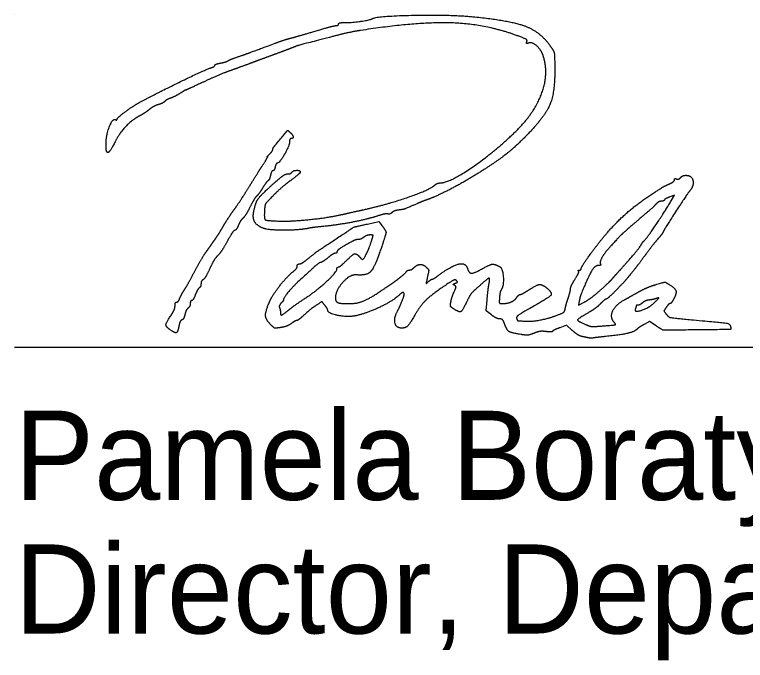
# Model space of a CAD drawing. Extents: x 0 to 34, y -1.6 to 22.
# Drawn here: x 24.528 to 25.676, y 8.599 to 9.614 of the extents above; entities that cross this region are included whole.
import ezdxf

# ---------------------------------------------------------------- set-up
doc = ezdxf.new("R2010")
doc.units = 0
doc.layers.add('SH_Data', color=7, linetype='Continuous')
doc.layers.add('SH_Text', color=7, linetype='Continuous')

msp = doc.modelspace()

# ---------------------------------------------------------------- linework, layer by layer
at = {"layer": 'SH_Data'}
for p, q in [((24.5279, 9.6139), (24.5279, 9.6139)), ((24.5279, 9.0916), (28.0279, 9.0916))]:
    msp.add_line(p, q, dxfattribs=at)
at = {"layer": 'SH_Text'}
for points in [[(25.5597, 9.3211), (25.5651, 9.33), (25.5577, 9.3274)], [(25.0824, 9.2849), (25.1004, 9.289), (25.1051, 9.2828)], [(25.2773, 9.1421), (25.269, 9.1484), (25.2704, 9.1655)], [(25.4153, 9.1641), (25.4143, 9.1576), (25.4229, 9.1621)], [(25.5361, 9.1248), (25.5255, 9.1316), (25.5171, 9.1271)], [(25.4043, 9.1178), (25.3951, 9.1261), (25.3845, 9.122)]]:
    msp.add_lwpolyline(points, dxfattribs=at)
for points in [[(25.0898, 9.6075), (25.0966, 9.6117), (25.2136, 9.614), (25.248, 9.6106)], [(25.0368, 9.5991), (25.0368, 9.6004), (25.0408, 9.6014), (25.0458, 9.6013)], [(25.0458, 9.6013), (25.0554, 9.601), (25.0864, 9.6054), (25.0898, 9.6075)], [(25.3205, 9.5798), (25.2699, 9.5988), (25.1619, 9.6028), (25.0716, 9.589)], [(25.248, 9.6106), (25.3072, 9.6047), (25.3548, 9.5865), (25.3706, 9.5634)], [(25, 9.5879), (25.0161, 9.5927), (25.031, 9.5966), (25.033, 9.5966)], [(25.033, 9.5966), (25.0351, 9.5966), (25.0368, 9.5977), (25.0368, 9.5991)], [(24.9612, 9.5768), (24.9665, 9.5781), (24.9839, 9.5831), (25, 9.5879)], [(25.0272, 9.5793), (24.9762, 9.5661), (24.9719, 9.5649), (24.9612, 9.5606)], [(25.0716, 9.589), (25.0623, 9.5876), (25.0424, 9.5833), (25.0272, 9.5793)], [(25.3328, 9.5712), (25.3338, 9.5737), (25.3303, 9.5761), (25.3205, 9.5798)], [(24.8808, 9.5483), (24.8955, 9.5534), (24.9019, 9.5558), (24.9372, 9.5689)], [(24.9372, 9.5689), (24.9451, 9.5719), (24.9559, 9.5754), (24.9612, 9.5768)], [(25.3352, 9.5691), (25.3326, 9.5681), (25.3319, 9.5688), (25.3328, 9.5712)], [(25.3586, 9.5492), (25.3553, 9.559), (25.3409, 9.5713), (25.3352, 9.5691)], [(24.9612, 9.5606), (24.9585, 9.5595), (24.9483, 9.5557), (24.9384, 9.5521)], [(25.3706, 9.5634), (25.3755, 9.5562), (25.3764, 9.5518), (25.3768, 9.534)], [(24.8628, 9.5412), (24.8641, 9.5421), (24.8722, 9.5454), (24.8808, 9.5483)], [(24.9384, 9.5521), (24.9285, 9.5485), (24.9134, 9.5429), (24.9048, 9.5397)], [(25.3131, 9.428), (25.344, 9.4575), (25.3679, 9.521), (25.3586, 9.5492)], [(24.837, 9.5305), (24.84, 9.5314), (24.8424, 9.533), (24.8424, 9.534)], [(24.8424, 9.534), (24.8424, 9.5351), (24.8464, 9.5368), (24.8514, 9.5377)], [(24.8514, 9.5377), (24.8563, 9.5386), (24.8615, 9.5402), (24.8628, 9.5412)], [(24.9048, 9.5397), (24.8962, 9.5364), (24.88, 9.5305), (24.8688, 9.5265)], [(25.3768, 9.534), (25.3775, 9.4932), (25.3614, 9.4535), (25.332, 9.4236)], [(24.7248, 9.4762), (24.755, 9.4924), (24.8286, 9.528), (24.837, 9.5305)], [(24.8688, 9.5265), (24.8576, 9.5226), (24.8372, 9.514), (24.8236, 9.5075)], [(24.8236, 9.5075), (24.8099, 9.5011), (24.7983, 9.4958), (24.7977, 9.4958)], [(24.7877, 9.4901), (24.7828, 9.487), (24.7761, 9.4836), (24.7729, 9.4826)], [(24.7977, 9.4958), (24.7971, 9.4958), (24.7927, 9.4932), (24.7877, 9.4901)], [(24.6888, 9.4495), (24.6888, 9.4517), (24.7142, 9.4705), (24.7248, 9.4762)], [(24.7637, 9.4774), (24.7619, 9.4756), (24.7576, 9.4735), (24.754, 9.4726)], [(24.7729, 9.4826), (24.7697, 9.4816), (24.7655, 9.4792), (24.7637, 9.4774)], [(24.7392, 9.4645), (24.7346, 9.4609), (24.7274, 9.4563), (24.7233, 9.4542)], [(24.754, 9.4726), (24.7505, 9.4717), (24.7438, 9.4681), (24.7392, 9.4645)], [(24.7233, 9.4542), (24.7129, 9.4489), (24.693, 9.428), (24.6868, 9.4159)], [(24.6716, 9.4117), (24.6717, 9.4249), (24.6823, 9.4515), (24.6865, 9.4489)], [(24.6865, 9.4489), (24.6877, 9.4481), (24.6888, 9.4484), (24.6888, 9.4495)], [(24.939, 9.4106), (24.9575, 9.4327), (24.9568, 9.4322), (24.9609, 9.4288)], [(24.9624, 9.419), (24.9611, 9.419), (24.96, 9.4167), (24.96, 9.4139)], [(24.9609, 9.4288), (24.9652, 9.4252), (24.9661, 9.419), (24.9624, 9.419)], [(25.1964, 9.3494), (25.2105, 9.3494), (25.2786, 9.3953), (25.3131, 9.428)], [(25.332, 9.4236), (25.3134, 9.4047), (25.281, 9.3798), (25.2505, 9.361)], [(24.673, 9.398), (24.6722, 9.3988), (24.6716, 9.4049), (24.6716, 9.4117)], [(24.6868, 9.4159), (24.6801, 9.403), (24.6748, 9.3961), (24.673, 9.398)], [(24.9336, 9.402), (24.9336, 9.4032), (24.936, 9.4071), (24.939, 9.4106)], [(24.96, 9.4139), (24.96, 9.4083), (24.9441, 9.3806), (24.9409, 9.3806)], [(24.925, 9.3902), (24.9245, 9.3902), (24.9261, 9.3923), (24.9288, 9.395)], [(24.9288, 9.395), (24.9314, 9.3976), (24.9336, 9.4007), (24.9336, 9.402)], [(24.916, 9.3745), (24.9216, 9.3831), (24.9256, 9.3902), (24.925, 9.3902)], [(24.894, 9.3395), (24.9006, 9.3501), (24.9105, 9.3659), (24.916, 9.3745)], [(24.9374, 9.3746), (24.9366, 9.3713), (24.9349, 9.3686), (24.9337, 9.3686)], [(24.9409, 9.3806), (24.9398, 9.3806), (24.9382, 9.3779), (24.9374, 9.3746)], [(24.9252, 9.3396), (24.9409, 9.3542), (24.9536, 9.3638), (24.9576, 9.3638)], [(24.93, 9.3614), (24.9291, 9.3574), (24.9274, 9.3536), (24.9261, 9.3528)], [(24.9337, 9.3686), (24.9325, 9.3686), (24.9309, 9.3653), (24.93, 9.3614)], [(24.9576, 9.3638), (24.9601, 9.3638), (24.9628, 9.3648), (24.9636, 9.3662)], [(24.9768, 9.3665), (24.9768, 9.3654), (24.97, 9.3595), (24.9618, 9.3534)], [(24.9636, 9.3662), (24.9654, 9.3691), (24.9768, 9.3694), (24.9768, 9.3665)], [(25.2505, 9.361), (25.2313, 9.3491), (25.1901, 9.3281), (25.176, 9.323)], [(25.5745, 9.3579), (25.5761, 9.3598), (25.5798, 9.3614), (25.5827, 9.3614)], [(25.5827, 9.3614), (25.5921, 9.3614), (25.5959, 9.3453), (25.5885, 9.3363)], [(24.9261, 9.3528), (24.9248, 9.352), (24.921, 9.3469), (24.9176, 9.3414)], [(24.9618, 9.3534), (24.9535, 9.3473), (24.941, 9.3364), (24.934, 9.3293)], [(25.1882, 9.346), (25.1903, 9.3479), (25.1939, 9.3494), (25.1964, 9.3494)], [(25.557, 9.348), (25.5613, 9.3499), (25.5648, 9.3528), (25.5648, 9.3543)], [(25.5648, 9.3543), (25.5648, 9.3558), (25.5663, 9.3565), (25.5682, 9.3558)], [(25.5682, 9.3558), (25.5701, 9.355), (25.5729, 9.356), (25.5745, 9.3579)], [(24.8722, 9.3065), (24.8776, 9.314), (24.8874, 9.3288), (24.894, 9.3395)], [(24.9038, 9.305), (24.9066, 9.318), (24.9127, 9.328), (24.9252, 9.3396)], [(24.9176, 9.3414), (24.9142, 9.3359), (24.9101, 9.3303), (24.9084, 9.3289)], [(25.0764, 9.3074), (25.1133, 9.3156), (25.1796, 9.3385), (25.1882, 9.346)], [(25.528, 9.331), (25.5469, 9.3432), (25.5488, 9.3443), (25.557, 9.348)], [(24.9084, 9.3289), (24.9068, 9.3276), (24.9021, 9.32), (24.8981, 9.312)], [(24.934, 9.3293), (24.9233, 9.3183), (24.9211, 9.3147), (24.9206, 9.3064)], [(25.4334, 9.2385), (25.4556, 9.2693), (25.5007, 9.3133), (25.528, 9.331)], [(25.5885, 9.3363), (25.5843, 9.3313), (25.5515, 9.2809), (25.5483, 9.2747)], [(25.5577, 9.3274), (25.5537, 9.326), (25.5498, 9.3239), (25.549, 9.3227)], [(25.1603, 9.3168), (25.1433, 9.3094), (25.1384, 9.3077), (25.1318, 9.3069)], [(25.176, 9.323), (25.1714, 9.3214), (25.1643, 9.3186), (25.1603, 9.3168)], [(25.5349, 9.3152), (25.5322, 9.3122), (25.5197, 9.3011), (25.5072, 9.2906)], [(25.5169, 9.2582), (25.5197, 9.2601), (25.5479, 9.3016), (25.5597, 9.3211)], [(25.5437, 9.3206), (25.5415, 9.3206), (25.5375, 9.3181), (25.5349, 9.3152)], [(25.549, 9.3227), (25.5483, 9.3215), (25.5459, 9.3206), (25.5437, 9.3206)], [(24.8555, 9.281), (24.8593, 9.2876), (24.8669, 9.2991), (24.8722, 9.3065)], [(24.8981, 9.312), (24.8941, 9.304), (24.889, 9.296), (24.8868, 9.2942)], [(24.9192, 9.2781), (24.9087, 9.282), (24.9016, 9.2945), (24.9038, 9.305)], [(24.9206, 9.3064), (24.9197, 9.293), (24.9238, 9.2901), (24.9444, 9.2895)], [(25.0428, 9.2999), (25.0507, 9.3017), (25.0658, 9.3051), (25.0764, 9.3074)], [(25.121, 9.3029), (25.1189, 9.3011), (25.1158, 9.3001), (25.1142, 9.3007)], [(25.1318, 9.3069), (25.1279, 9.3065), (25.123, 9.3047), (25.121, 9.3029)], [(24.8868, 9.2942), (24.8847, 9.2924), (24.8814, 9.2873), (24.8796, 9.2829)], [(24.9444, 9.2895), (24.9636, 9.289), (25.0215, 9.2951), (25.0428, 9.2999)], [(25.0962, 9.2969), (25.0797, 9.2917), (25.0346, 9.2832), (25.0108, 9.2809)], [(25.1142, 9.3007), (25.1125, 9.3013), (25.1044, 9.2996), (25.0962, 9.2969)], [(24.8425, 9.2603), (24.8458, 9.2651), (24.8517, 9.2744), (24.8555, 9.281)], [(24.8796, 9.2829), (24.8777, 9.2786), (24.8752, 9.275), (24.8739, 9.275)], [(25.0108, 9.2809), (25.0025, 9.2801), (24.9933, 9.2789), (24.9904, 9.2783)], [(25.0284, 9.2585), (25.06, 9.2795), (25.0614, 9.2802), (25.0824, 9.2849)], [(25.1051, 9.2828), (25.1117, 9.274), (25.1115, 9.2692), (25.1038, 9.2466)], [(25.5072, 9.2906), (25.4876, 9.2741), (25.4759, 9.2627), (25.4592, 9.2438)], [(24.8739, 9.275), (24.8726, 9.275), (24.8672, 9.2671), (24.8618, 9.2574)], [(24.9904, 9.2783), (24.9767, 9.2752), (24.9272, 9.2751), (24.9192, 9.2781)], [(25.5483, 9.2747), (25.5466, 9.2712), (25.5427, 9.2658), (25.5397, 9.2626)], [(24.8289, 9.2411), (24.833, 9.2469), (24.8391, 9.2556), (24.8425, 9.2603)], [(24.8618, 9.2574), (24.8565, 9.2477), (24.8498, 9.2377), (24.847, 9.2352)], [(24.9892, 9.2306), (25.0029, 9.2416), (25.0009, 9.2403), (25.0284, 9.2585)], [(25.0581, 9.2574), (25.0436, 9.2495), (25.0344, 9.2431), (25.0344, 9.2411)], [(25.0678, 9.2606), (25.0656, 9.2606), (25.0612, 9.2591), (25.0581, 9.2574)], [(25.0765, 9.2641), (25.074, 9.2621), (25.07, 9.2606), (25.0678, 9.2606)], [(25.075, 9.2294), (25.0768, 9.2294), (25.0866, 9.2505), (25.0897, 9.2612)], [(25.0864, 9.2677), (25.0835, 9.2676), (25.0791, 9.266), (25.0765, 9.2641)], [(25.0897, 9.2612), (25.0914, 9.2669), (25.091, 9.2677), (25.0864, 9.2677)], [(25.513, 9.253), (25.5142, 9.2552), (25.5159, 9.2575), (25.5169, 9.2582)], [(25.5397, 9.2626), (25.5367, 9.2593), (25.5278, 9.248), (25.5199, 9.2373)], [(25.1038, 9.2466), (25.0935, 9.2167), (25.0815, 9.2036), (25.0656, 9.205)], [(25.4817, 9.2152), (25.497, 9.2323), (25.5106, 9.2487), (25.513, 9.253)], [(24.81, 9.209), (24.8163, 9.2208), (24.8248, 9.2353), (24.8289, 9.2411)], [(24.847, 9.2352), (24.8441, 9.2326), (24.8386, 9.2235), (24.8347, 9.215)], [(25.0317, 9.239), (25.0303, 9.239), (25.025, 9.2357), (25.02, 9.2318)], [(25.0344, 9.2411), (25.0344, 9.2399), (25.0332, 9.239), (25.0317, 9.239)], [(25.0488, 9.227), (25.0589, 9.2371), (25.0654, 9.2389), (25.0704, 9.233)], [(25.4184, 9.2151), (25.4184, 9.2165), (25.4251, 9.227), (25.4334, 9.2385)], [(25.4592, 9.2438), (25.4533, 9.2372), (25.4471, 9.2243), (25.4485, 9.2219)], [(25.5199, 9.2373), (25.512, 9.2267), (25.5043, 9.2165), (25.5029, 9.2147)], [(24.972, 9.2187), (24.972, 9.2206), (24.9735, 9.2222), (24.9754, 9.2222)], [(25.0088, 9.2245), (25.0069, 9.2245), (24.9985, 9.2173), (24.9732, 9.194)], [(24.9754, 9.2222), (24.9772, 9.2222), (24.9834, 9.2259), (24.9892, 9.2306)], [(25.02, 9.2318), (25.015, 9.2278), (25.01, 9.2245), (25.0088, 9.2245)], [(25.0368, 9.2174), (25.0381, 9.2174), (25.0435, 9.2217), (25.0488, 9.227)], [(25.0704, 9.233), (25.072, 9.231), (25.0741, 9.2294), (25.075, 9.2294)], [(25.1935, 9.2039), (25.2138, 9.2191), (25.2365, 9.2247), (25.2395, 9.2152)], [(24.8347, 9.215), (24.8307, 9.2064), (24.826, 9.1985), (24.8242, 9.1974)], [(24.9285, 9.1627), (24.933, 9.1731), (24.9562, 9.2026), (24.9666, 9.2109)], [(24.9666, 9.2109), (24.9695, 9.2133), (24.972, 9.2168), (24.972, 9.2187)], [(24.9883, 9.1708), (25.0039, 9.1812), (25.0344, 9.2099), (25.0344, 9.2142)], [(25.0344, 9.2142), (25.0344, 9.2159), (25.0355, 9.2174), (25.0368, 9.2174)], [(25.1431, 9.2095), (25.1442, 9.2112), (25.1465, 9.2126), (25.1483, 9.2126)], [(25.1483, 9.2126), (25.1501, 9.2126), (25.1534, 9.2143), (25.1555, 9.2165)], [(25.1555, 9.2165), (25.1605, 9.2214), (25.1705, 9.2215), (25.1754, 9.2165)], [(25.1754, 9.2165), (25.1786, 9.2134), (25.1788, 9.2109), (25.1767, 9.2018)], [(25.2395, 9.2152), (25.2419, 9.2076), (25.25, 9.2075), (25.2633, 9.2149)], [(25.2633, 9.2149), (25.2752, 9.2215), (25.2825, 9.2222), (25.2907, 9.2176)], [(25.2907, 9.2176), (25.2951, 9.2151), (25.2967, 9.1871), (25.2928, 9.182)], [(25.4086, 9.1983), (25.4125, 9.2045), (25.415, 9.2103), (25.4142, 9.2111)], [(25.4142, 9.2111), (25.4134, 9.2119), (25.414, 9.2126), (25.4156, 9.2126)], [(25.4156, 9.2126), (25.4171, 9.2126), (25.4184, 9.2137), (25.4184, 9.2151)], [(25.4462, 9.2198), (25.4399, 9.2198), (25.4304, 9.2046), (25.4183, 9.1754)], [(25.4485, 9.2219), (25.4493, 9.2207), (25.4482, 9.2198), (25.4462, 9.2198)], [(25.4661, 9.1977), (25.4692, 9.2013), (25.4762, 9.2091), (25.4817, 9.2152)], [(25.5029, 9.2147), (25.4896, 9.1982), (25.485, 9.1931), (25.4732, 9.1809)], [(24.7946, 9.1814), (24.7968, 9.1847), (24.8037, 9.1971), (24.81, 9.209)], [(25.0656, 9.205), (25.0552, 9.2059), (25.032, 9.1805), (25.032, 9.1682)], [(25.1004, 9.1777), (25.119, 9.19), (25.1414, 9.2067), (25.1431, 9.2095)], [(25.1767, 9.2018), (25.1744, 9.1915), (25.1745, 9.191), (25.1783, 9.1945)], [(25.1841, 9.1982), (25.1851, 9.1982), (25.1893, 9.2007), (25.1935, 9.2039)], [(25.2734, 9.1904), (25.2752, 9.1998), (25.2726, 9.2002), (25.2633, 9.192)], [(24.8208, 9.191), (24.8208, 9.1885), (24.8197, 9.1857), (24.8183, 9.1849)], [(24.8242, 9.1974), (24.8223, 9.1964), (24.8208, 9.1935), (24.8208, 9.191)], [(24.9732, 9.194), (24.9641, 9.1856), (24.9504, 9.1686), (24.9504, 9.1656)], [(25.1783, 9.1945), (25.1805, 9.1965), (25.1832, 9.1982), (25.1841, 9.1982)], [(25.2222, 9.1961), (25.2204, 9.1979), (25.2145, 9.1951), (25.202, 9.1866)], [(25.2194, 9.1884), (25.2172, 9.1898), (25.2175, 9.1907), (25.2206, 9.1919)], [(25.2187, 9.1786), (25.2215, 9.1849), (25.2217, 9.187), (25.2194, 9.1884)], [(25.2206, 9.1919), (25.2236, 9.193), (25.224, 9.1943), (25.2222, 9.1961)], [(25.2633, 9.192), (25.2474, 9.178), (25.2437, 9.1736), (25.2382, 9.1622)], [(25.2704, 9.1655), (25.2712, 9.1749), (25.2726, 9.1861), (25.2734, 9.1904)], [(25.336, 9.1814), (25.3489, 9.1896), (25.3565, 9.1904), (25.3642, 9.1843)], [(25.4016, 9.1835), (25.4016, 9.1853), (25.4047, 9.192), (25.4086, 9.1983)], [(25.446, 9.1789), (25.4539, 9.1857), (25.4629, 9.1942), (25.4661, 9.1977)], [(25.506, 9.1769), (25.5139, 9.1814), (25.5271, 9.1871), (25.5353, 9.1896)], [(25.5353, 9.1896), (25.5493, 9.1938), (25.5505, 9.1938), (25.5564, 9.19)], [(25.5564, 9.19), (25.566, 9.1837), (25.5684, 9.1763), (25.5638, 9.1673)], [(24.7877, 9.1688), (24.7893, 9.1724), (24.7924, 9.1781), (24.7946, 9.1814)], [(24.8183, 9.1849), (24.8169, 9.184), (24.8141, 9.1791), (24.812, 9.174)], [(25.0519, 9.1598), (25.065, 9.1598), (25.0841, 9.1668), (25.1004, 9.1777)], [(25.14, 9.1744), (25.14, 9.1775), (25.136, 9.177), (25.1324, 9.1735)], [(25.202, 9.1866), (25.1823, 9.1732), (25.1651, 9.1561), (25.1568, 9.1418)], [(25.2136, 9.163), (25.2144, 9.1671), (25.2166, 9.1742), (25.2187, 9.1786)], [(25.2928, 9.182), (25.2916, 9.1803), (25.2903, 9.1746), (25.2899, 9.1694)], [(25.3224, 9.1742), (25.3236, 9.1742), (25.3297, 9.1774), (25.336, 9.1814)], [(25.3642, 9.1843), (25.3739, 9.1767), (25.367, 9.1688), (25.3354, 9.1511)], [(25.3981, 9.1694), (25.4, 9.1753), (25.4016, 9.1817), (25.4016, 9.1835)], [(25.4229, 9.1621), (25.4277, 9.1645), (25.4381, 9.1721), (25.446, 9.1789)], [(25.4732, 9.1809), (25.4657, 9.1732), (25.4586, 9.167), (25.4576, 9.167)], [(25.4864, 9.1659), (25.4893, 9.1674), (25.4981, 9.1724), (25.506, 9.1769)], [(24.7824, 9.1622), (24.7838, 9.1622), (24.7862, 9.1651), (24.7877, 9.1688)], [(24.812, 9.174), (24.81, 9.1688), (24.8073, 9.1646), (24.8061, 9.1646)], [(24.9504, 9.1656), (24.9504, 9.1648), (24.9487, 9.1625), (24.9466, 9.1605)], [(24.9568, 9.1484), (24.9643, 9.1545), (24.9696, 9.1583), (24.9883, 9.1708)], [(25.032, 9.1682), (25.032, 9.1631), (25.0398, 9.1598), (25.0519, 9.1598)], [(25.1324, 9.1735), (25.1228, 9.1644), (25.084, 9.1456), (25.0656, 9.1411)], [(25.1294, 9.1478), (25.1335, 9.1554), (25.14, 9.1717), (25.14, 9.1744)], [(25.2899, 9.1694), (25.2894, 9.1618), (25.2901, 9.1598), (25.2932, 9.1598)], [(25.2932, 9.1598), (25.3016, 9.1598), (25.3136, 9.1646), (25.3168, 9.1693)], [(25.3168, 9.1693), (25.3187, 9.172), (25.3212, 9.1742), (25.3224, 9.1742)], [(25.3933, 9.1523), (25.394, 9.1557), (25.3961, 9.1634), (25.3981, 9.1694)], [(25.4183, 9.1754), (25.4172, 9.1727), (25.4159, 9.1676), (25.4153, 9.1641)], [(25.4576, 9.167), (25.4565, 9.167), (25.4526, 9.1638), (25.449, 9.16)], [(25.4694, 9.1315), (25.4633, 9.1389), (25.4731, 9.1587), (25.4864, 9.1659)], [(25.5254, 9.1655), (25.5215, 9.165), (25.5166, 9.1629), (25.5144, 9.161)], [(25.5372, 9.1682), (25.5345, 9.1672), (25.5292, 9.166), (25.5254, 9.1655)], [(25.5348, 9.1627), (25.5403, 9.1683), (25.5408, 9.1696), (25.5372, 9.1682)], [(25.5638, 9.1673), (25.5616, 9.1631), (25.5589, 9.1598), (25.5578, 9.1598)], [(24.7742, 9.1423), (24.7774, 9.147), (24.78, 9.1534), (24.78, 9.1565)], [(24.78, 9.1565), (24.78, 9.1596), (24.7811, 9.1622), (24.7824, 9.1622)], [(24.804, 9.16), (24.804, 9.1576), (24.8024, 9.1543), (24.8005, 9.1527)], [(24.8061, 9.1646), (24.8049, 9.1646), (24.804, 9.1625), (24.804, 9.16)], [(24.9302, 9.127), (24.9225, 9.1346), (24.9219, 9.1474), (24.9285, 9.1627)], [(24.9466, 9.1605), (24.9446, 9.1584), (24.9435, 9.1552), (24.9442, 9.1532)], [(24.9442, 9.1532), (24.945, 9.1513), (24.9456, 9.1482), (24.9456, 9.1464)], [(25.0041, 9.1586), (24.9959, 9.1532), (24.9933, 9.1512), (24.9821, 9.1412)], [(25.0154, 9.1572), (25.0109, 9.163), (25.0108, 9.163), (25.0041, 9.1586)], [(25.0199, 9.1498), (25.0199, 9.1507), (25.0179, 9.154), (25.0154, 9.1572)], [(25.2182, 9.1514), (25.2132, 9.1547), (25.2124, 9.1567), (25.2136, 9.163)], [(25.2382, 9.1622), (25.2315, 9.1485), (25.2267, 9.1459), (25.2182, 9.1514)], [(25.449, 9.16), (25.4454, 9.1562), (25.4373, 9.1501), (25.431, 9.1464)], [(25.5033, 9.1516), (25.5008, 9.1451), (25.5263, 9.154), (25.5348, 9.1627)], [(25.5048, 9.1564), (25.5048, 9.1558), (25.5041, 9.1537), (25.5033, 9.1516)], [(25.5076, 9.1574), (25.506, 9.1574), (25.5048, 9.1569), (25.5048, 9.1564)], [(25.5144, 9.161), (25.5122, 9.159), (25.5091, 9.1574), (25.5076, 9.1574)], [(25.5519, 9.1539), (25.5484, 9.1486), (25.5484, 9.1477), (25.5523, 9.143)], [(25.5578, 9.1598), (25.5567, 9.1598), (25.554, 9.1571), (25.5519, 9.1539)], [(24.7725, 9.1186), (24.7655, 9.1234), (24.7659, 9.1301), (24.7742, 9.1423)], [(24.7955, 9.1426), (24.7946, 9.1387), (24.7925, 9.1349), (24.7908, 9.1342)], [(24.8005, 9.1527), (24.7986, 9.1511), (24.7964, 9.1466), (24.7955, 9.1426)], [(24.9456, 9.1464), (24.9456, 9.1415), (24.949, 9.1421), (24.9568, 9.1484)], [(25.0656, 9.1411), (25.0527, 9.1381), (25.0201, 9.1442), (25.0199, 9.1498)], [(25.1361, 9.1214), (25.1277, 9.1214), (25.1237, 9.1372), (25.1294, 9.1478)], [(25.1568, 9.1418), (25.1486, 9.1276), (25.1422, 9.1214), (25.1361, 9.1214)], [(25.2903, 9.1358), (25.2877, 9.1358), (25.2819, 9.1386), (25.2773, 9.1421)], [(25.3354, 9.1511), (25.3222, 9.1436), (25.316, 9.1388), (25.3168, 9.1366)], [(25.3806, 9.1417), (25.3894, 9.145), (25.3923, 9.1475), (25.3933, 9.1523)], [(25.431, 9.1464), (25.4131, 9.136), (25.412, 9.1327), (25.425, 9.1272)], [(25.5523, 9.143), (25.5559, 9.1385), (25.5609, 9.1375), (25.5948, 9.1343)], [(24.7908, 9.1342), (24.7891, 9.1336), (24.787, 9.1294), (24.7862, 9.125)], [(24.9714, 9.1334), (24.9703, 9.1334), (24.9665, 9.1312), (24.9629, 9.1286)], [(24.9821, 9.1412), (24.9773, 9.1369), (24.9725, 9.1334), (24.9714, 9.1334)], [(25.2978, 9.128), (25.296, 9.1331), (25.2934, 9.1358), (25.2903, 9.1358)], [(25.3168, 9.1366), (25.3181, 9.1332), (25.3188, 9.133), (25.3308, 9.1323)], [(25.3308, 9.1323), (25.3413, 9.1317), (25.3674, 9.1366), (25.3806, 9.1417)], [(25.4518, 9.1247), (25.4713, 9.1263), (25.4731, 9.127), (25.4694, 9.1315)], [(25.5948, 9.1343), (25.6439, 9.1298), (25.6521, 9.1282), (25.6531, 9.1235)], [(24.7862, 9.125), (24.7843, 9.1153), (24.7801, 9.1133), (24.7725, 9.1186)], [(24.9464, 9.1223), (24.9377, 9.121), (24.9355, 9.1216), (24.9302, 9.127)], [(24.9629, 9.1286), (24.9593, 9.126), (24.9519, 9.1232), (24.9464, 9.1223)], [(25.3232, 9.1114), (25.3082, 9.1138), (25.3013, 9.1183), (25.2978, 9.128)], [(25.3845, 9.122), (25.3787, 9.1197), (25.3737, 9.1172), (25.3733, 9.1163)], [(25.425, 9.1272), (25.4318, 9.1242), (25.4383, 9.1237), (25.4518, 9.1247)], [(25.5054, 9.1192), (25.5017, 9.1155), (25.4802, 9.1106), (25.4568, 9.1082)], [(25.5171, 9.1271), (25.5125, 9.1246), (25.5072, 9.1211), (25.5054, 9.1192)], [(25.5828, 9.1184), (25.5471, 9.118), (25.5467, 9.118), (25.5361, 9.1248)], [(25.6531, 9.1235), (25.6539, 9.1192), (25.6519, 9.1191), (25.5828, 9.1184)], [(25.3443, 9.1134), (25.3373, 9.1106), (25.3318, 9.1101), (25.3232, 9.1114)], [(25.3632, 9.1159), (25.3574, 9.1167), (25.3501, 9.1157), (25.3443, 9.1134)], [(25.3733, 9.1163), (25.3729, 9.1154), (25.3683, 9.1152), (25.3632, 9.1159)], [(25.4189, 9.1083), (25.4159, 9.109), (25.4093, 9.1132), (25.4043, 9.1178)], [(25.4292, 9.1062), (25.4265, 9.1067), (25.4219, 9.1077), (25.4189, 9.1083)], [(25.4568, 9.1082), (25.4482, 9.1073), (25.4396, 9.1063), (25.4376, 9.1059)], [(25.4376, 9.1059), (25.4356, 9.1055), (25.4318, 9.1056), (25.4292, 9.1062)]]:
    msp.add_open_spline(points, degree=2, dxfattribs=at)

# ---------------------------------------------------------------- texts
for s, p in [('Pamela Boratyn', (24.5279, 8.8516)), ('Director, Department of Transportation', (24.5279, 8.6416))]:
    msp.add_text(s, height=0.14, dxfattribs=at).set_placement(p)

doc.saveas('drawing.dxf')
